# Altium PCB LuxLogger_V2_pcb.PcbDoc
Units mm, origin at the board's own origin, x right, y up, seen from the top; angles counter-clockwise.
Board outline 63.83 x 29.23 mm, 4 copper layers (Layer 1, Layer 2 - GND, Layer 3 - PWR, Layer 4), stack 1.57 mm thick; 85 components, 62 nets, 282 pads, 83 vias.
Unrouted connection lines stored in the file: 1.
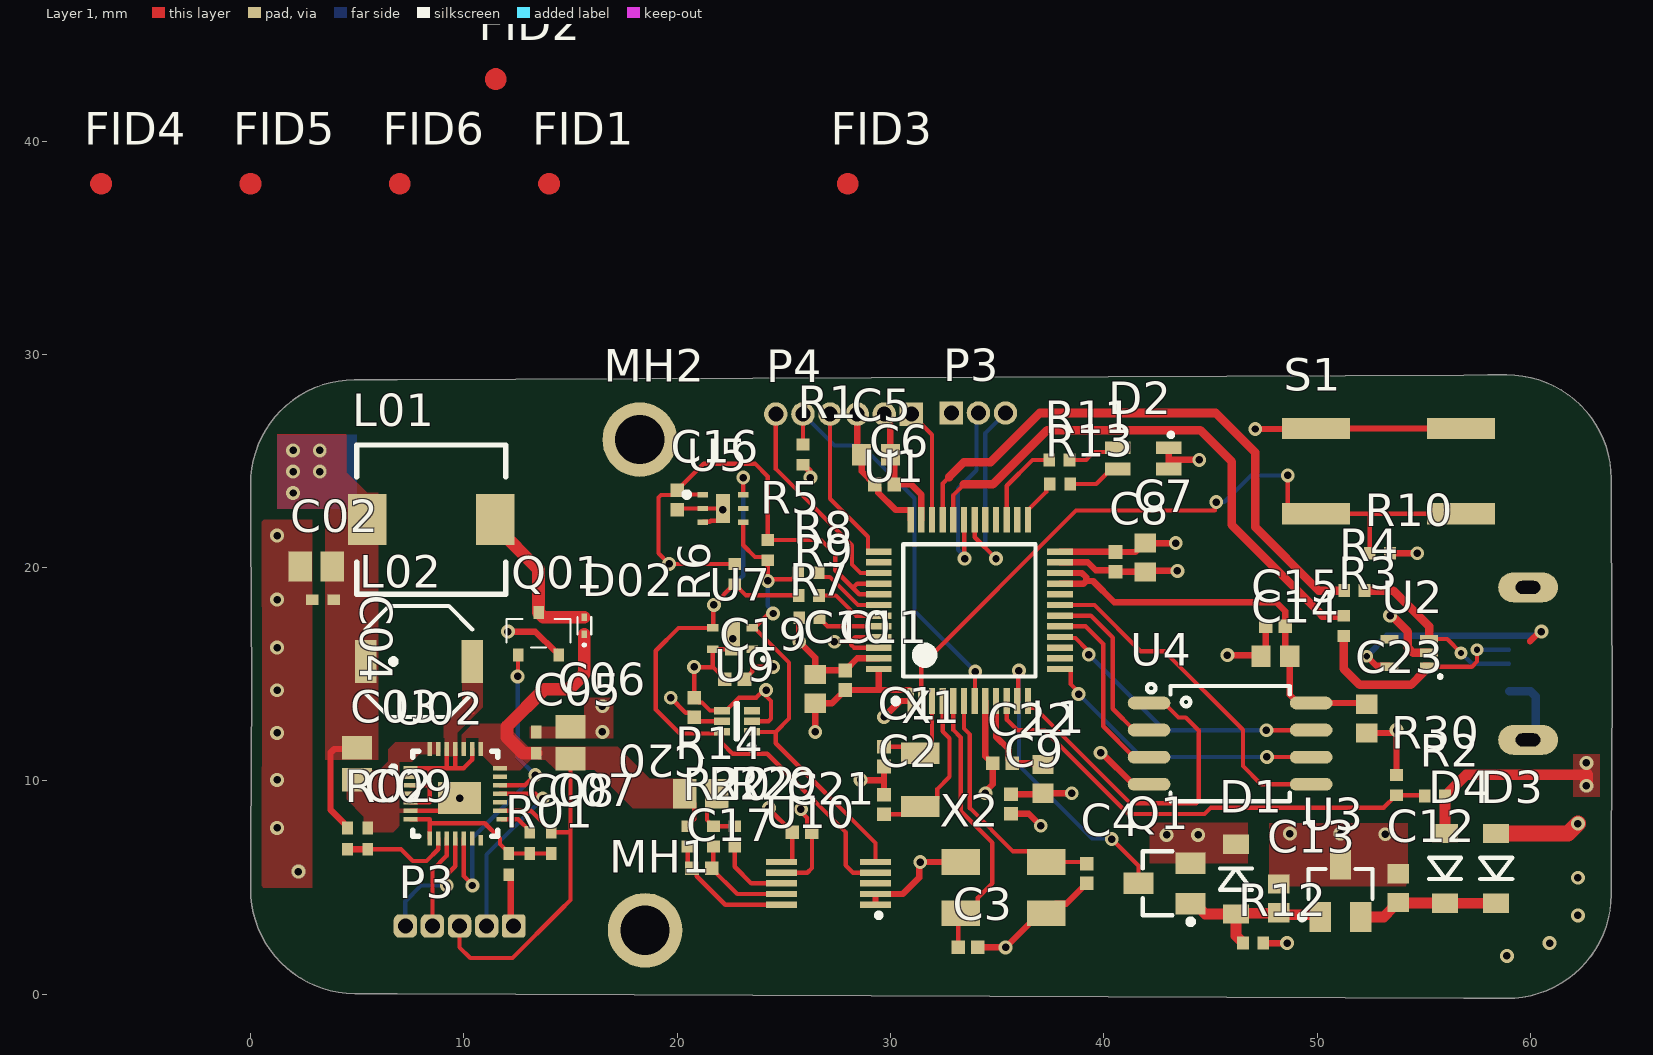
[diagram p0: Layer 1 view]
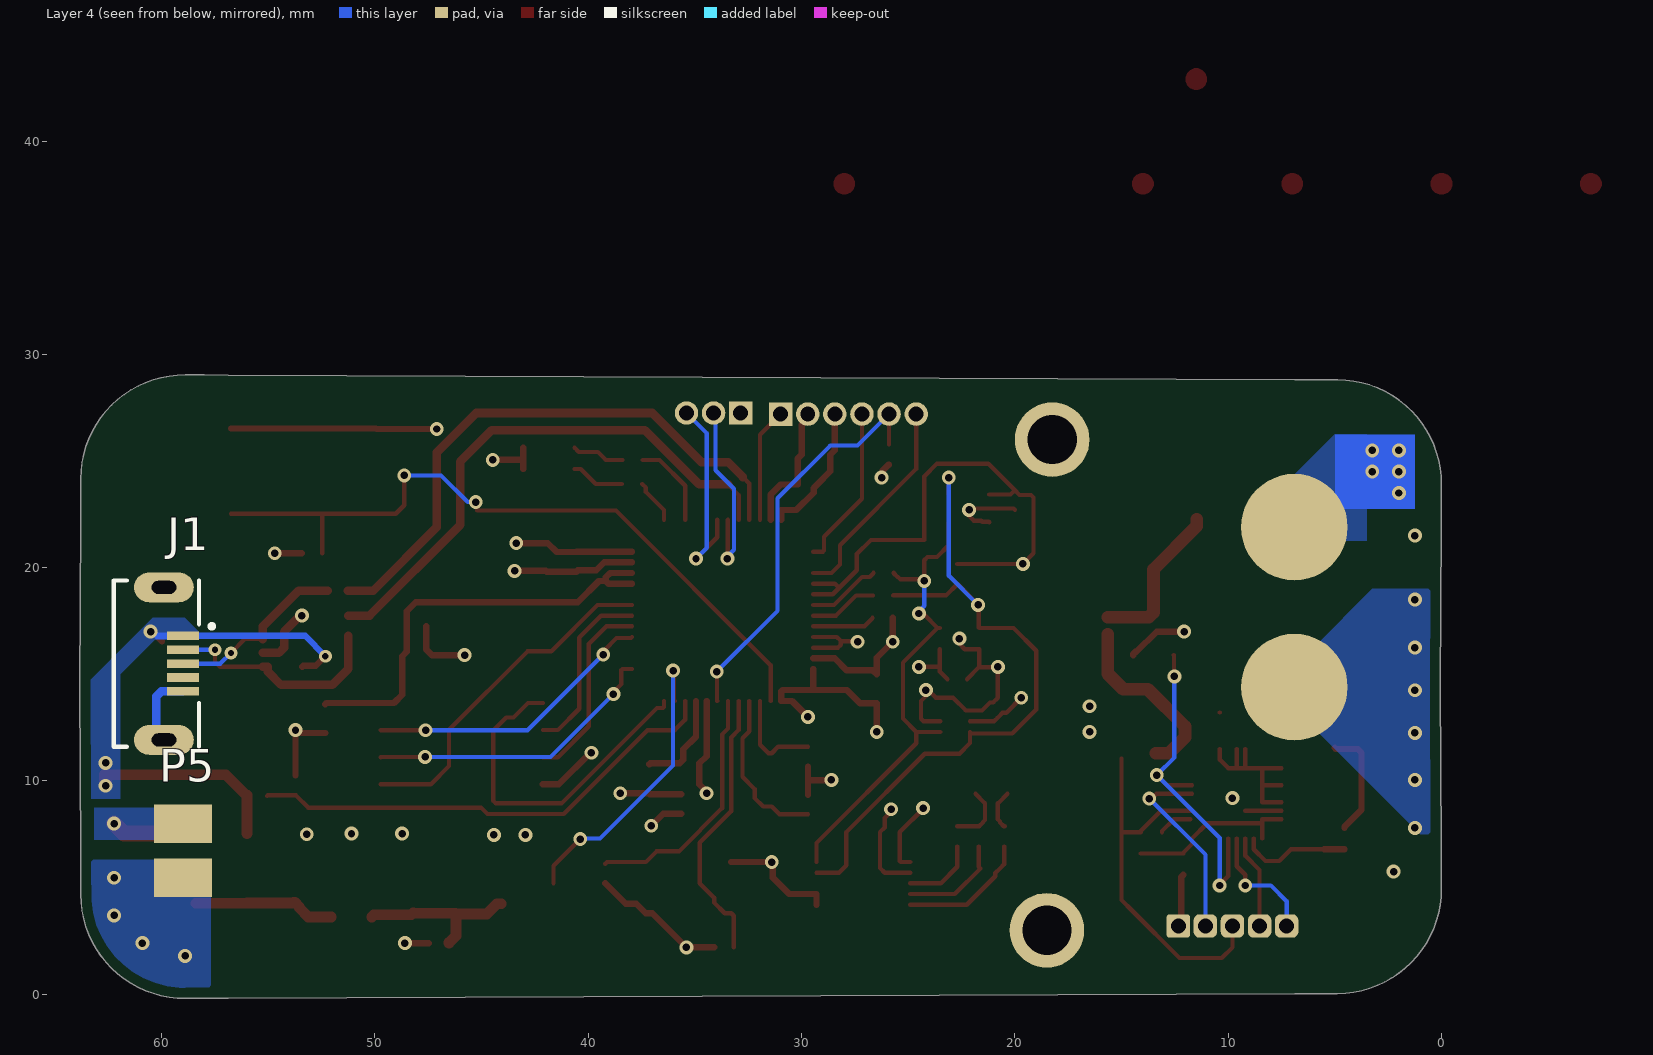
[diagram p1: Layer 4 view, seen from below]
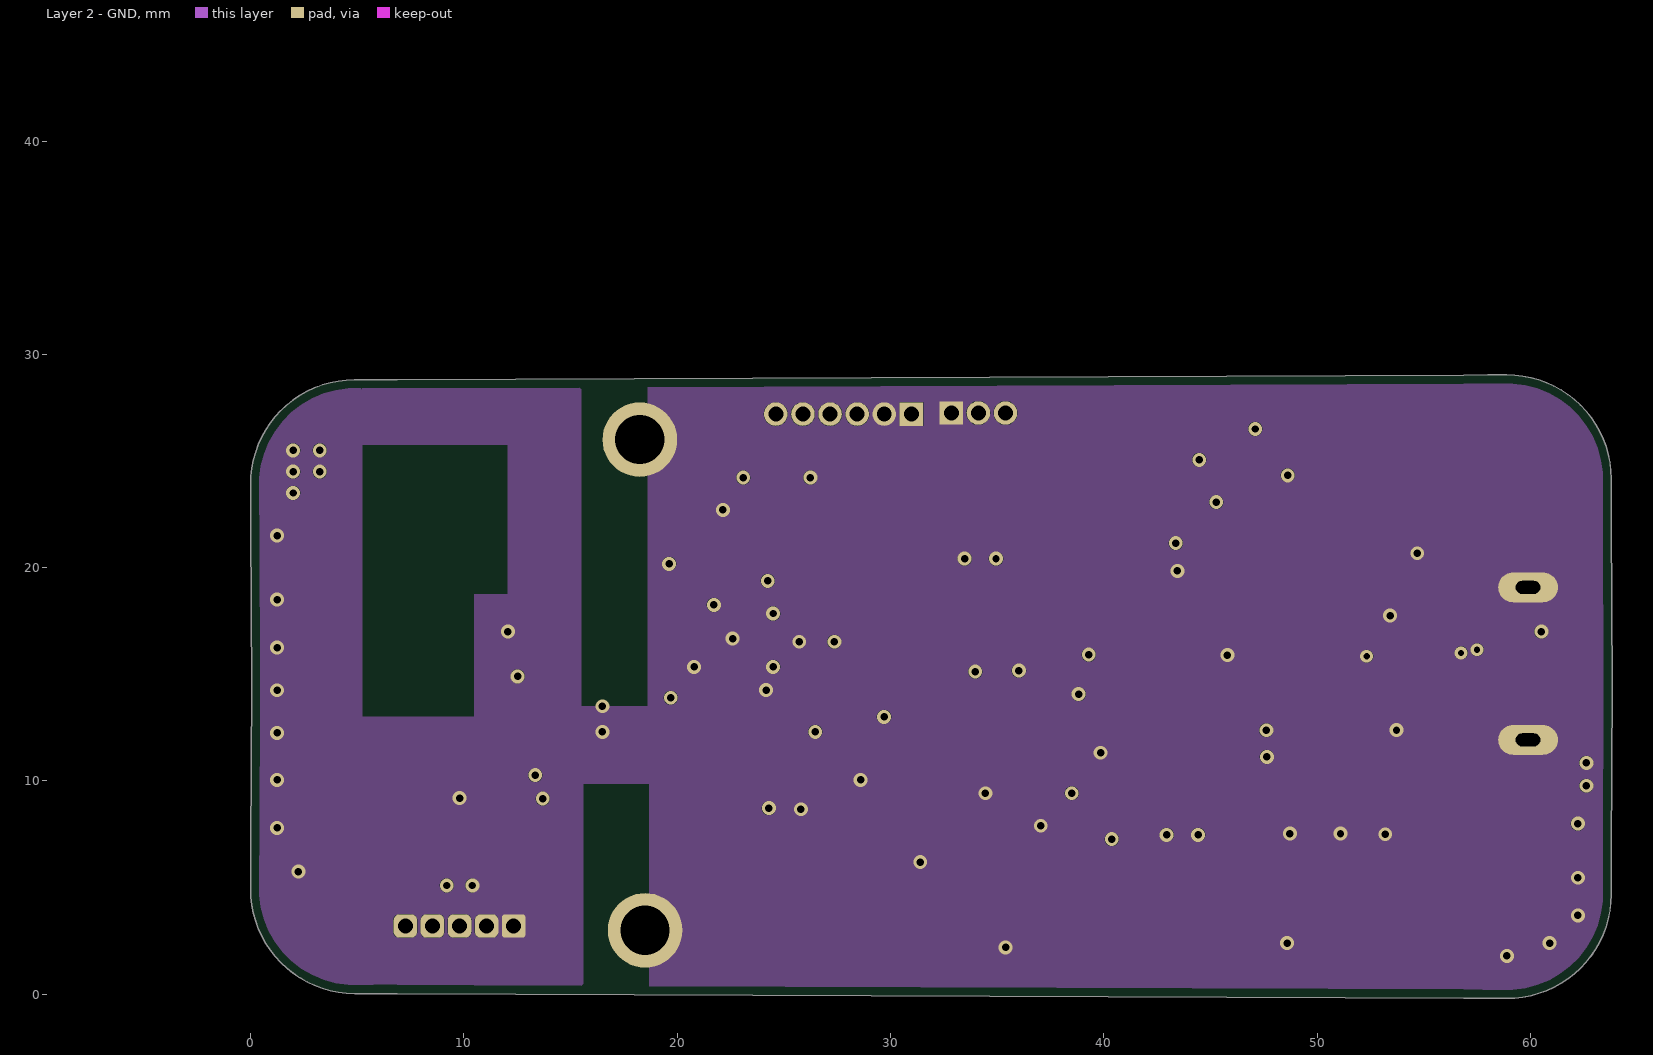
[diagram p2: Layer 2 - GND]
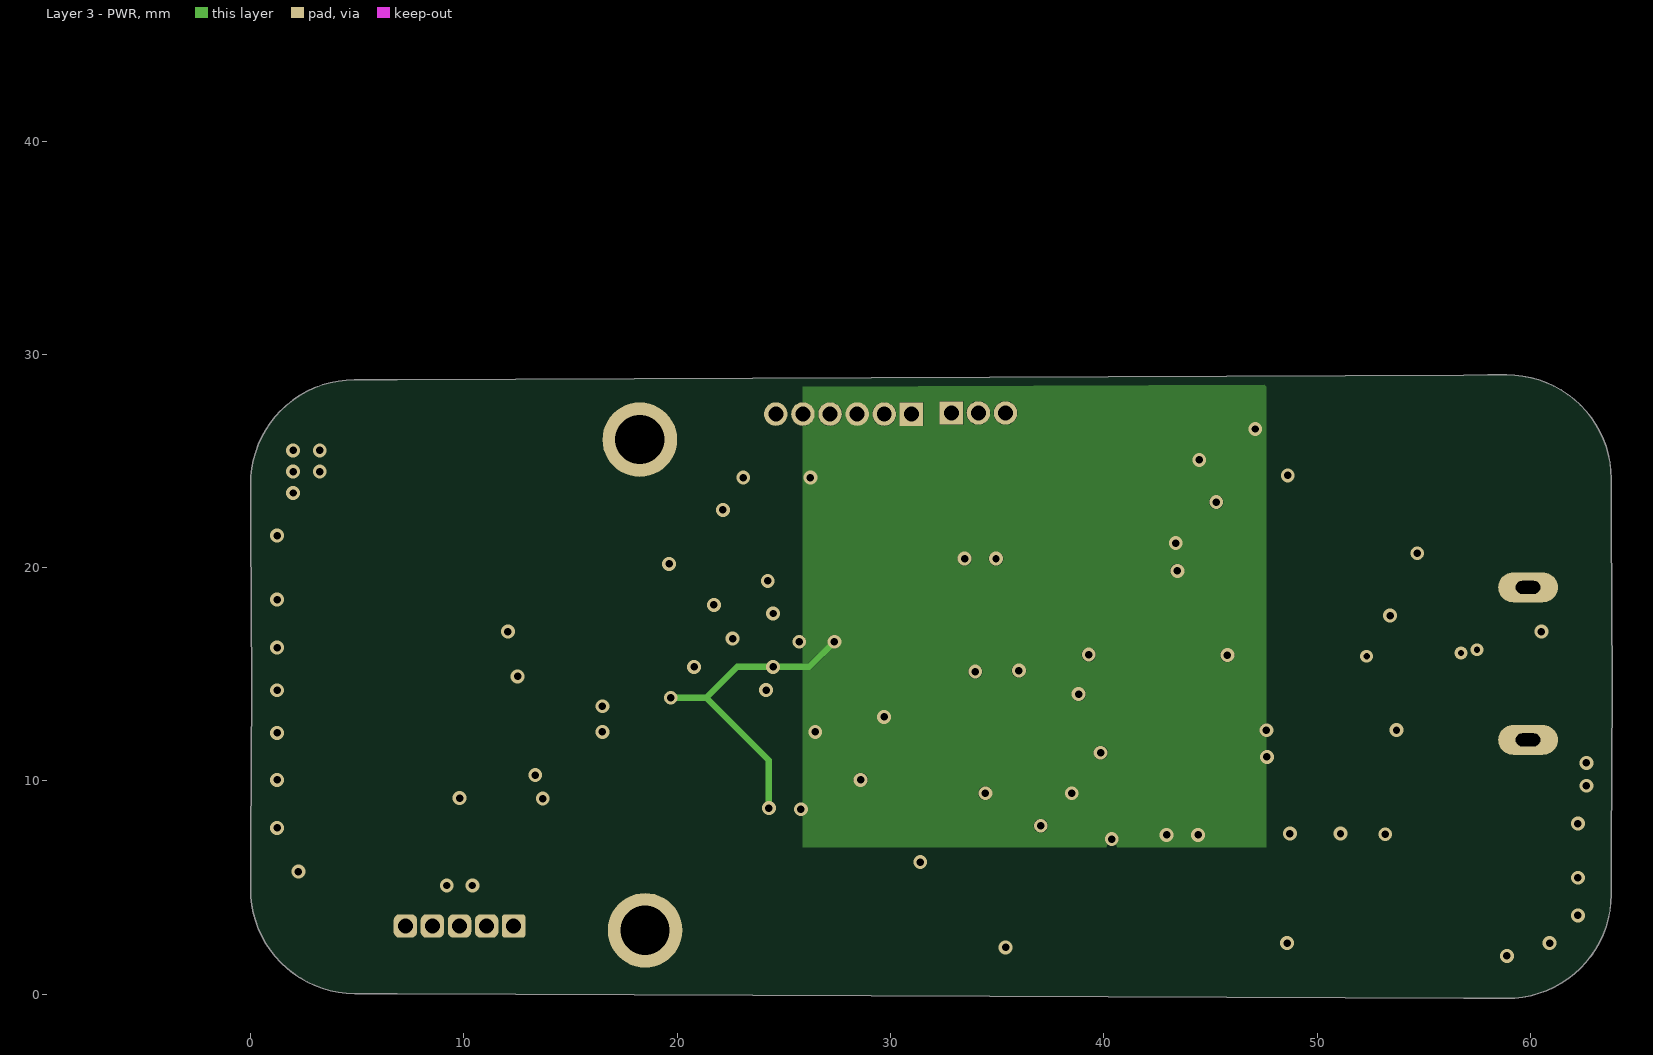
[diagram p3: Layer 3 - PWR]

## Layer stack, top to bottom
Top Solder: solder mask 0.01, Solder Resist, Dk 3.5
Layer 1: signal copper 0.035
Dielectric 1: core 0.36, FR-4, Dk 4.8
Layer 2 - GND: signal copper 0.035
Dielectric 3: prepreg 0.71, Dk 4.2
Layer 3 - PWR: signal copper 0.035
Dielectric 4: core 0.36, Dk 4.2
Layer 4: signal copper 0.035
Bottom Solder: solder mask 0.01, Solder Resist, Dk 3.5

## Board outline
4.878,0.035 cw(c4.896,4.925) 0.006,4.949 0.013,6.068 0.017,6.951 0.049,14.422 0.017,21.893 0.012,23.016 0.006,23.895 cw(c4.896,23.919) 4.878,28.809 5.998,28.811 6.881,28.815 56.881,29.027 58.004,29.032 58.883,29.037 cw(c58.907,24.148) 63.797,24.165 63.799,23.046 63.803,22.163 63.836,14.422 63.803,6.681 63.799,5.557 63.797,4.678 cw(c58.907,4.696) 58.883,-0.194 57.764,-0.187 56.881,-0.183 6.881,0.029 5.757,0.033

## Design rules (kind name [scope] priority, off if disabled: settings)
BoardOutlineClearance "BoardOutlineClearance inner layers" [OnLayer('Layer 2 - GND') OR OnLayer('Layer 3 - PWR')] p1: gap=0.4 ignorepadtopadclearanceinfootprint=FALSE
BoardOutlineClearance [OnLayer('Layer 1') OR OnLayer('Layer 4')] p2: gap=0.5 ignorepadtopadclearanceinfootprint=FALSE
Clearance "Clearance tmp112" [HasFootprint('SOTFL50P160X60-6N')] p1: gap=0.15 ignorepadtopadclearanceinfootprint=FALSE
Clearance "Clearance outer layers" [OnLayer('Layer 1') OR OnLayer('Layer 4')] p2: gap=0.2 ignorepadtopadclearanceinfootprint=FALSE
Clearance "Clearance inner layers" [OnLayer('Layer 2') OR OnLayer('Layer 3')] p3: gap=0.2 ignorepadtopadclearanceinfootprint=FALSE
ComponentClearance "ComponentClearance power options" [HasFootprint('BU2032SM-HD-G') vs HasFootprint('JST_S2B-PH-SM4-TB') OR HasFootprint('SOD123 SODFL360X130-2N')] p1: gap=0 collisioncheckmode=3 verticalgap=0 showdistances=FALSE
ComponentClearance "ComponentClearance power options_1" [All vs HasFootprint('HOLE_PLATED_2900um')] p2: gap=0 collisioncheckmode=3 verticalgap=0 showdistances=FALSE
ComponentClearance "ComponentClearance FID" [HasFootprint('FIDUCIAL_01')] p3: gap=0 collisioncheckmode=3 verticalgap=0 showdistances=FALSE
ComponentClearance [All] p4: gap=0.2 collisioncheckmode=3 verticalgap=2540 showdistances=FALSE
DiffPairsRouting "DiffPairsRouting USB 90R diff" [InDifferentialPair('USB')] p1: maxlimit=0.3 minlimit=0.15 mostfreqgap=0.3 toplayer_minwidth=0.2 toplayer_maxwidth=0.6 toplayer_prefwidth=0.6 midlayer1_mingap=0.254 midlayer1_maxgap=0.254 midlayer1_prefgap=0.254 midlayer1_minwidth=0.381 midlayer1_maxwidth=0.381 midlayer1_prefwidth=0.381 midlayer2_mingap=0.254 midlayer2_maxgap=0.254 midlayer2_prefgap=0.254 midlayer2_minwidth=0.381 midlayer2_maxwidth=0.381 midlayer2_prefwidth=0.381 bottomlayer_minwidth=0.2 bottomlayer_maxwidth=0.6 bottomlayer_prefwidth=0.6 maxuncoupledlength=12.7
HoleSize [All] p1: absolutevalues=TRUE maxlimit=4 minlimit=0.3 maxpercent=80.000 minpercent=20.000
PlaneClearance [All] p1: clearance=0.2
PlaneConnect [All] p1: planeconnectstyle=Direct reliefexpansion=0.508 reliefentries=4 reliefconductorwidth=0.254 reliefairgap=0.254
PolygonConnect [All] p1: connectstyle=Direct reliefconductorwidth=0.3 reliefentries=4 polygonreliefangle="90 Angle" airgapwidth=0.2
RoutingVias [All] p1: holewidth=0.3 width=0.6 viastyle="Through Hole" minholewidth=0.3 minwidth=0.6 maxholewidth=0.5 maxwidth=1
SolderMaskExpansion [All] p1: expansion=0.102 istentingtop=FALSE
UnRoutedNet [All] p1: checkbadconnections=TRUE
Width [All] p1: maxlimit=2 minlimit=0.15 preferedwidth=0.2 toplayer_minwidth=0.2 bottomlayer_minwidth=0.2 minimp=50.000000 maximp=50.000000 favimp=50.000000
24 further rules are at their usual default settings.

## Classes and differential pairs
component class Sunboost: C02 C03 C04 C05 C06 C07 C08 C09 D02 L01 L02 P3 Q01 R01 R02 U02
differential pair USB: +USB_P -USB_N

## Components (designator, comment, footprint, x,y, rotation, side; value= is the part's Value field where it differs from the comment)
C1 "" CAP0402 29.7,11.14 r90 top
C02 "Cap_0805" 0805 3.075,20.05 r0 top value=22uF
C2 "" CAP0402 29.7,8.9 r270 top
C03 "Cap_0805" 0805 5,10.8 r90 top value=22uF
C3 "" CAP0402 33.64,2.2 r180 top
C04 "Cap_0402" 0402 3.4,18.5 r0 top value=100nF
C4 "" CAP0402 39.2,5.66 r90 top
C05 "Cap_0402" 0402 13.4,11.8 r270 top value=100nF
C5 "" CAP0603 29.325,25.3 r180 top
C06 "Cap_0805" 0805 15,11.8 r270 top value=22uF
C6 "" CAP0402 29.725,23.9 r180 top
C07 "Cap_0402" 0402 14.1,7.1 r90 top value=100nF
C7 "" CAP0603 41.95,20.475 r90 top
C08 "Cap_0402" 0402 13.1,7.1 r90 top value=470nF
C8 "" CAP0402 40.55,20.275 r90 top
C09 "Cap_0402" 0402 5.5,7.3 r270 top value=100nF
C9 "" CAP0402 35.65,8.925 r90 top
C10 "" CAP0603 26.475,14.322 r270 top
C11 "" CAP0402 27.875,14.722 r270 top
C12 "" CAP0603 53.8,4.975 r270 top
C13 "" CAP0603 48.2,4.5 r270 top
C14 "" CAP0603 48.05,15.85 r0 top
C15 "" CAP0402 48.05,17.25 r0 top
C16 "" CAP0402 20,23.169 r90 top
C17 "" CAP0402 21.16,5.9 r180 top
C19 "" CAP0402 22.7,14.772 r0 top
C20 "" CAP0402 20.8,13.44 r270 top
C21 "" CAP0402 25.86,7.6 r180 top
C22 "" CAP0402 35.25,10.825 r0 top
C23 "" CAP0603 52.325,12.925 r90 top
D1 "Alternative ON BAT54T1GOSCT-ND" "SOD123 SODFL360X130-2N" 46.2,5.4 r90 top
D02 "NSR0140P2" SOD-923 15.65,16.875 r90 top
D2 "" KPTBD-3216SURKCGKC 40.65,25.625 r0 top
D3 "Alternative ON BAT54T1GOSCT-ND" "SOD123 SODFL360X130-2N" 58.4,5.9 r270 top
D4 "Alternative ON BAT54T1GOSCT-ND" "SOD123 SODFL360X130-2N" 56,5.9 r270 top
FID1 "Fiducial" FIDUCIAL_02_small 14,38 r90 top
FID2 "Fiducial" FIDUCIAL_02_small 11.5,42.9 r90 top
FID3 "Fiducial" FIDUCIAL_02_small 28,38 r90 top
FID4 "Fiducial" FIDUCIAL_02_small -7,38 r90 top
FID5 "Fiducial" FIDUCIAL_02_small 0,38 r90 top
FID6 "Fiducial" FIDUCIAL_02_small 7,38 r90 top
J1 "USB3140-30-0170-1-C_REVE1" GCT_USB3140-30-0170-1-C_REVE1 60.25,15.5 r270 bottom
L01 "SRR7045-102M" SRR7045-102M 5.475,22.25 r0 top value=X
L1 "" CAP0603 37.15,10.1 r90 top
L02 "SD53-4R7-R" SD53-4R7-R 7.9,15.6 r0 top value=X
MH1 "Mounting hole" HOLE_PLATED_2300um 18.5,3 r0 top
MH2 "Mounting hole" HOLE_PLATED_2300um 18.25,26 r0 top
P3 "1x5 Header" "1x5 Header 1.27" 12.34,3.2 r180 top
P3 "" "Header 1x3 1.27" 32.855,27.25 r0 top
P4 "" "Header 1x6 1.27" 30.98,27.2 r180 top
P5 "" "2x1 blank pads_2" 59,6.73 r270 bottom
Q01 "PMV130ENE" SOT-23 12.557,15.9 r0 top
Q1 "" SOT23-3 42.7,5.2 r180 top
R01 "Res_0402" 0402 12.1,6.1 r270 top value=0
R1 "" RES0402 25.9,25.3 r270 top
R02 "Res_0402" 0402 4.55,7.3 r270 top value=51K
R2 "" RES0402 55.525,9.3 r0 top
R3 "" RES0402 51.25,17.275 r270 top
R4 "" RES0402 51.75,18.925 r0 top
R5 "" RES0402 24.25,20.825 r90 top
R6 "" RES0402 22.7,19.7 r90 top
R7 "" RES0402 26.2,17.65 r0 top
R8 "" RES0402 26.151,19.765 r0 top
R9 "" RES0402 26.176,18.69 r0 top
R10 "" RES0402 52.95,20.675 r180 top
R11 "" RES0402 37.925,25.05 r180 top
R12 "" RES0402 47,2.4 r180 top
R13 "" RES0402 37.95,23.925 r180 top
R14 "Res_0805" 0805 21.1,9.4 r180 top value=1K
R20 "" RES0402 20.5,7.4 r270 top
R22 "" RES0402 21.7,7.4 r270 top
R29 "" RES0402 22.7,7.4 r270 top
R30 "" RES0402 53.725,9.8 r270 top
S1 "" EVQQ2W02W 56.75,26.525 r180 top
U1 "" TSQFP50P900X900X160-48N 33.7,18 r90 top
U02 "Sunboost 3" 28-QFN_0.4mm 7.5,10.6 r0 top
U2 "" "SC-70 5L" 55.25,15.35 r90 top
U3 "" SOT23-3 51.1,5 r90 top
U4 "" SO_8_W 45.925,11.75 r0 top
U5 "" OPT3001 21.2,23.425 r0 top
U7 "" SHTC3 23.525,16.172 r90 top
U9 "" SOTFL50P160X60-6N 22.8,12.8 r180 top
U10 "" VSSOP-10 27.2,5.2 r180 top
X1 "" FC-135 31.4,11.3 r270 top
X2 "" ABM3B 35.3,5 r0 top

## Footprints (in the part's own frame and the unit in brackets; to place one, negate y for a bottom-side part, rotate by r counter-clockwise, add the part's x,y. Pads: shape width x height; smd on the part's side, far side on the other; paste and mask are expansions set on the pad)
"1x5 Header 1.27" [mm]
  rrect25% 1.1x1.1 hole 0.7 paste+0 mask+0: 1(0,0)
  rrect50% 1.1x1.1 hole 0.7 paste+0 mask+0: 2(1.27,0) 3(2.54,0) 4(3.81,0) 5(5.08,0)
"2x1 blank pads_2" [mm]
  rect 1.8x2.7 smd: 1(-1.27,0) 2(1.27,0)
28-QFN_0.4mm [mm]
  rect 0.65x0.2 smd mask+0.05: 1(0,0) 2(0,-0.4) 3(0,-0.8) 4(0,-1.2) 5(0,-1.6) 6(0,-2) 7(0,-2.4) 16(4.2,-2) 17(4.2,-1.6) 18(4.2,-1.2) 19(4.2,-0.8) 20(4.2,-0.4) 21(4.2,0)
  rect 0.2x0.65 smd mask+0.05: 8(0.9,-3.3) 9(1.3,-3.3) 10(1.7,-3.3) 11(2.1,-3.3) 12(2.5,-3.3) 13(2.9,-3.3) 22(3.3,0.9) 23(2.9,0.9) 24(2.5,0.9) 25(2.1,0.9) 26(1.7,0.9) 27(1.3,0.9) 28(0.9,0.9)
  rect 0.2x0.5 smd mask+0.05: 14(3.3,-3.375)
  rect 0.5x0.2 smd mask+0.05: 15(4.275,-2.4)
  rect 2x1.5 smd mask+0.05: 29(2.3,-1.4)
  silkscreen extent -0.9,-3.2 4.1,0.8, body extent 0.1,-3.2 4.1,0.8, height 0.75
0402 [mm] "Chip Capacitor, Body 1.0x0.5mm, IPC High Density"
  rect 0.6x0.5 smd: 1(-0.5,0) 2(0.5,0)
  body extent -0.55,-0.3 0.55,0.3, height 1.3
0805 [mm] "Chip Capacitor, Body 2.0x1.3mm, IPC High Density"
  rect 1.1x1.4 smd: 1(-0.75,0) 2(0.75,0)
  body extent -1.1,-0.72 1.1,0.72, height 1.4
ABM3B [mm]
  rect 1.8x1.2 smd: 1(-2,-1.2) 2(2,-1.2) 3(2,1.2) 4(-2,1.2)
  body extent -2.5,-1.6 2.5,1.6, height 1.1
CAP0402 [mm]
  rect 0.64x0.64 smd: 1(-0.46,0) 2(0.46,0)
  body extent -0.55,-0.3 0.55,0.3, height 0.6
CAP0603 [mm]
  rect 0.9x1 smd: 1(-0.675,0) 2(0.675,0)
  body extent -0.87,-0.48 0.87,0.47, height 0.85
EVQQ2W02W [mm]
  rect 3.2x1 smd: 1(0,0) 2(6.8,0) 3(6.8,4) 4(0,4)
  body extent 0,-1 6.5,5, height 2.5
FC-135 [mm]
  rect 1x1.8 smd: 1(0,0) 2(2.5,0)
  body extent -0.35,-0.75 2.85,0.75, height 0.8
FIDUCIAL_02_small [mm]
  Layer 1 region: 0,-0.5 -0.099,-0.5 -0.283,-0.424 -0.424,-0.283 -0.5,-0.099 -0.5,0 -0.5,0.099 -0.424,0.283 -0.283,0.424 -0.099,0.5 0,0.5 0.099,0.5 0.283,0.424 0.424,0.283 0.5,0.099 0.5,0 0.5,-0.099 0.424,-0.283 0.283,-0.424 0.099,-0.5 0,-0.5
  Layer 1 pour cut-out: 0,-1 -0.098,-1 -0.292,-0.962 -0.474,-0.886 -0.637,-0.777 -0.777,-0.637 -0.886,-0.474 -0.962,-0.292 -1,-0.098 -1,0 -1,0.098 -0.962,0.292 -0.886,0.474 -0.777,0.637 -0.637,0.777 -0.474,0.886 -0.292,0.962 -0.098,1 0,1 0.098,1 0.292,0.962 0.474,0.886 0.637,0.777 0.777,0.637 0.886,0.474 0.962,0.292 1,0.098 1,0 1,-0.098 0.962,-0.292 0.886,-0.474 0.777,-0.637 0.637,-0.777 0.474,-0.886 0.292,-0.962 0.098,-1 0,-1
GCT_USB3140-30-0170-1-C_REVE1 [mm]
  rect 0.4x1.5 smd: 1(-1.3,1.25) 2(-0.65,1.25) 3(0,1.25) 4(0.65,1.25) 5(1.3,1.25)
  oval 1.4x2.8 hole 0.6 slot 1.15 at 90 deg mask+0: S1(-3.575,0.36) S2(3.575,0.36)
  silkscreen extent -3.9,-2 3.9,2.7
"Header 1x3 1.27" [mm]
  rect 1.1x1.1 hole 0.7: 1(0,0)
  round 1.1 hole 0.7: 2(1.27,0) 3(2.54,0)
"Header 1x6 1.27" [mm]
  rect 1.1x1.1 hole 0.7: 1(0,0)
  round 1.1 hole 0.7: 2(1.27,0) 3(2.54,0) 4(3.81,0) 5(5.08,0) 6(6.35,0)
HOLE_PLATED_2300um [mm]
  round 3.5 hole 2.3: 1(0,0)
KPTBD-3216SURKCGKC [mm]
  rect 1.2x0.6 smd: 1(2.4,0) 2(0,0) 3(2.4,-1) 4(0,-1)
  silkscreen extent 2.4,0.5 2.6,0.7, body extent -0.4,-1.3 2.8,0.3, height 1.8
OPT3001 [mm]
  rect 0.5x0.25 smd: 1(0,0) 2(0,-0.65) 3(0,-1.3) 4(1.9,-1.3) 5(1.9,-0.65) 6(1.9,0)
  rect 0.65x1.35 smd: 7(0.95,-0.65)
  silkscreen extent -0.87,-0.12 -0.63,0.12, body extent -0.05,-1.65 1.95,0.35, height 0.62
RES0402 [mm]
  rect 0.55x0.6 smd: 1(-0.475,0) 2(0.475,0)
  body extent -0.55,-0.3 0.55,0.3, height 0.4
"SC-70 5L" [mm]
  rect 0.4x0.85 smd: 1(0,0) 2(0.65,0) 3(1.3,0) 4(1.3,1.85) 5(0,1.85)
  silkscreen extent -0.51,-0.58 -0.4,-0.47, body extent -0.45,0.25 1.75,1.6, height 1.1
SD53-4R7-R [mm]
  rect 1x2 smd mask+0.05: 1(-2.5,0) 2(2.5,0)
  silkscreen extent -2.5,-2.6 2.5,2.6, body extent -2.6,-2.6 2.6,2.6, height 3
SHTC3 [mm]
  rect 0.35x0.55 smd: 1(0,0) 2(1,0) 3(1,1.85) 4(0,1.85)
  rect 1.6x0.7 smd: 5(0.5,0.925)
  silkscreen extent -0.51,-0.58 -0.4,-0.47, body extent -0.5,-0.07 1.5,1.93, height 0.75
SO_8_W [mm]
  oval 2x0.6 smd: 1(-3.8,1.905) 2(-3.8,0.635) 3(-3.8,-0.635) 4(-3.8,-1.905) 5(3.8,-1.905) 6(3.8,-0.635) 7(3.8,0.635) 8(3.8,1.905)
  silkscreen extent -3.9,-2.7 2.8,2.8, body extent -4.05,-2.73 4.05,2.73, height 1.75
"SOD123 SODFL360X130-2N" [mm]
  rect 0.91x1.22 smd: 1(-1.635,0) 2(1.635,0)
  silkscreen extent -0.5,-0.75 0.5,0.75, body extent -1.4,-0.85 1.4,0.85, height 1.3
SOD-923 [mm]
  rect 0.36x0.25 smd mask+0.05: 1(0,0) 2(0.8,0)
  silkscreen extent -0.52,-0.33 0.8,0.33, body extent -0.12,-0.32 0.93,0.32, height 0.43
SOT23-3 [mm]
  rect 1.4x1 smd: 1(-1.375,0.95) 2(-1.375,-0.95) 3(1.075,0)
  silkscreen extent -1.5,-1.5 0.87,1.92, body extent -1.7,-1.5 1.3,1.5, height 1.1
SOT-23 [mm]
  rect 0.5x0.6 smd mask+0.05: 1(0,0) 2(1.9,0) 3(0.95,2)
  silkscreen extent -0.55,0.35 2.45,1.7, body extent -0.55,-0.25 2.45,2.25, height 1.1
SOTFL50P160X60-6N [mm]
  rect 0.75x0.35 smd: 1(-0.7,0.5) 2(-0.7,0) 3(-0.7,-0.5) 4(0.7,-0.5) 5(0.7,0) 6(0.7,0.5)
  silkscreen extent -0.83,-0.85 0.05,1.35, body extent -0.85,-0.85 0.85,0.85, height 0.6
SRR7045-102M [mm]
  rect 1.8x2.4 smd mask+0.05: 1(0,0) 2(6,0)
  silkscreen extent -0.5,-3.5 6.5,3.5, body extent -0.5,-3.5 6.5,3.5, height 4.5
TSQFP50P900X900X160-48N [mm]
  rect 1.2x0.3 smd: 1(-4.25,2.75) 2(-4.25,2.25) 3(-4.25,1.75) 4(-4.25,1.25) 5(-4.25,0.75) 6(-4.25,0.25) 7(-4.25,-0.25) 8(-4.25,-0.75) 9(-4.25,-1.25) 10(-4.25,-1.75) 11(-4.25,-2.25) 12(-4.25,-2.75) 25(4.25,-2.75) 26(4.25,-2.25) 27(4.25,-1.75) 28(4.25,-1.25) 29(4.25,-0.75) 30(4.25,-0.25) 31(4.25,0.25) 32(4.25,0.75) 33(4.25,1.25) 34(4.25,1.75) 35(4.25,2.25) 36(4.25,2.75)
  rect 0.3x1.2 smd: 13(-2.75,-4.25) 14(-2.25,-4.25) 15(-1.75,-4.25) 16(-1.25,-4.25) 17(-0.75,-4.25) 18(-0.25,-4.25) 19(0.25,-4.25) 20(0.75,-4.25) 21(1.25,-4.25) 22(1.75,-4.25) 23(2.25,-4.25) 24(2.75,-4.25) 37(2.75,4.25) 38(2.25,4.25) 39(1.75,4.25) 40(1.25,4.25) 41(0.75,4.25) 42(0.25,4.25) 43(-0.25,4.25) 44(-0.75,4.25) 45(-1.25,4.25) 46(-1.75,4.25) 47(-2.25,4.25) 48(-2.75,4.25)
  silkscreen extent -4.37,-3.1 3.1,3.57, body extent -3.5,-3.5 3.5,3.5, height 1.6
VSSOP-10 [mm]
  rect 1.45x0.3 smd: 1(-2.1,1) 2(-2.1,0.5) 3(-2.1,0) 4(-2.1,-0.5) 5(-2.1,-1) 6(2.3,-1) 7(2.3,-0.5) 8(2.3,0) 9(2.3,0.5) 10(2.3,1)
  silkscreen extent -2.35,1.4 -2.15,1.6, body extent -2.35,-1.5 2.55,1.5, height 1.15

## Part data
C1 C2 C3 C4 C6 C8 C9 C11 C15 C16 C17 C19 C20 C21 C22: library part Cap, "Capacitor", Package=0402
C02 C03 C04 C05 C06 C07 C08 C09: "Capacitor"
C5 C7 C10 C12 C13 C14 C23: library part Cap, "Capacitor", Package=0603
D1 D3 D4: library part "D Schottky", "Schottky Diode", Manufacturer=NEXPERIA, Manufacturer PN=BAT54GW, Package=SOD123
D02: "Typical INFRARED GaAs LED"
D2: library part LED_RG, "Red/green LED", Manufacturer=KINGBRIGHT, Manufacturer PN=KPTBD-3216SURKCGKC, Package=SMD
J1: "USB - micro B USB 2.0 Receptacle Connector 5 Position Surface Mount, Through Hole", Package=None
L01 L02: "Inductor"
L1: library part Inductor, "Inductor", Manufacturer=MURATA, Manufacturer PN=BLM18AG601SN1D, Package=0603
P3: library part "Header 3", "Header, 3-Pin", Package=Hole
P4: library part "Header 6", "Header, 6-Pin", Package=Hole
P5: library part "Header 2", "Header, 2-Pin", Package=SMD
Q01: "N-Channel MOSFET"
Q1: library part MOSFET-P, "P-Channel MOSFET", Manufacturer=ON, Manufacturer PN=FDN342P, Package=SOT-23
R01 R02 R14: "Resistor"
R1 R2 R3 R4 R5 R6 R7 R8 R9 R10 R11 R12 R13 R20 R22 R29 R30: library part Res2, "Resistor", Package=0402
S1: library part SW_EVQQ2, "Switch", Manufacturer=PANASONIC, Manufacturer PN=EVQQ2W02W, Package=SMD
U1: library part STM32L412CB_2, "MCU", Manufacturer=ST, Manufacturer PN=STM32L412CBT6, Package=LQFP-48
U02: "Initvation Sunboost 3"
U2: library part RClamp0503F, "TVS array USB", Manufacturer=SEMTECH, Manufacturer PN=RClamp0503F.TCT, Package=SC70-5L
U3: library part MCP1810TxxxTT, "3V3 LDO low iq", Manufacturer=MICROCHIP, Manufacturer PN=MCP1810T33ITT, Package=SOT23
U4: library part MX25R6435F_SO8, "ULTRA LOW POWER, 64M-BIT FLASH MEMORY", Manufacturer=Macronix, Manufacturer PN=MX25R6435FM2IL0, Package=SOIC-8
U5: library part OPT3001, "Lux sensor", Manufacturer=TI, Manufacturer PN=OPT3001DNP, Package=DNP-6
U7: library part SHTC3, "SHTC3 RH sensor", Manufacturer=SENSIRION, Package=DFN
U9: library part TMP112A, "Temp_Sensor", Manufacturer=TI, Manufacturer PN=TMP112AIDR, Package=SOT-563
U10: "Current and power monitor", Manufacturer=TI, Manufacturer PN=INA226AIDGS, Package=VSSOP10
X1: "32.768 kHz Crystal", Manufacturer=EPSON, Manufacturer PN="FC-135 32.7680KA-A5", Package=SMD
X2: "Crystal", Manufacturer=ABRACON, Manufacturer PN=ABM3B-8.000MHZ-B2-T, Package=SMD

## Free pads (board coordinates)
  round 5 smd far side mask+0.05: 1(6.9,14.4) 2(6.9,21.9)

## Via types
v1: diameter 0.65, hole 0.35, Layer 1 to Layer 4, tented both sides, 80 vias
v2: diameter 0.6, hole 0.3, Layer 1 to Layer 4, 3 vias

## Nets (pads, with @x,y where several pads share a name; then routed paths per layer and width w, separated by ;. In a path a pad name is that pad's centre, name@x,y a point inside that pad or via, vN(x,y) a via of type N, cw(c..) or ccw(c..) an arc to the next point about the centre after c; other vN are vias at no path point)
5V_USB: D4.1 J1.1 R2.2 U2.5 | length 20
  Layer 1 w0.3: v2(52.325,15.85) 52.782,15.393 53.357,15.393 U2.5 ; 59.984,16.55 60.434,17 v1(60.515,17)
  Layer 1 w0.5: D4.1 R2.2 56,9.325 56.025,9.35 56.05,9.35 56.989,10.289 62.625,10.289
  Layer 1 w0.6: v1(62.625,9.775) 62.625,10.289
  Layer 4 w0.3: v2(52.325,15.85) 53.275,16.8 J1.1 60.234,16.8 60.434,17 v1(60.515,17)
  other v1: 62.625,10.85
ACTIVATE_IV_MEASn: U1.20
BAT_MEAS: Q1.3 U1.11 | length 14.3
  Layer 1 w0.2: U1.11 35.987,13.787 35.987,15.137 v1(36.025,15.175) ; v1(40.375,7.275) 41.625,6.025 Q1.3
  Layer 4 w0.2: v1(36.025,15.175) 36.025,10.725 39.449,7.301 40.349,7.301 v1(40.375,7.275)
BUTTON: R10.2 S1.3 S1.4 U1.2 | length 34.3
  Layer 1 w0.2: U1.2 31.45,15.424 38.701,22.675 45.201,22.675 45.201,23.001 v1(45.275,23.075) ; v1(48.625,24.325) 48.625,22.925 49.025,22.525 S1.3 52.48,22.525 ; R10.2 52.475,22.52 52.48,22.525 ; S1.4 52.48,22.525
  Layer 4 w0.2: v1(45.275,23.075) 45.65,23.075 46.9,24.325 v1(48.625,24.325)
DGND: C07.1 C08.1 R01.1 U02.7 U02.8 | length 8.3
  Layer 1 w0.2: U02.7 8.4,8.2 8.4,8.015 ; U02.8 8.4,8.015 ; C07.1 C08.1 R01.1 12.1,6.65 11.7,7.05 11.7,7.3 10.985,8.015 8.4,8.015
EXT_BAT: D3.1 P5.1 R14.1 R22.1 R29.1 | length 6.9
  Layer 1 w0.2: R14.1 21.4,8.95 21.4,8.175 21.5,8.075 21.5,8.05 21.675,7.875 R22.1 R29.1
  Layer 1 w0.75: D3.1 61.76,7.535 v1(62.225,8)
FLASH_CS: U1.12 U4.1 | length 16.4
  Layer 1 w0.2: U1.12 36.45,13.467 36.5,13.417 36.783,13.417 41.25,8.95 44.333,8.95 44.45,9.067 44.45,12.375 43.848,12.977 43.503,12.977 42.825,13.655 U4.1
FLASH_SCLK: U1.13 U4.6 | length 13.9
  Layer 1 w0.2: U1.13 38.4,15.25 38.45,15.2 38.45,14.549 38.825,14.174 v1(38.825,14.075) ; v1(47.65,11.125) 47.655,11.12 49.72,11.12 U4.6
  Layer 4 w0.2: v1(38.825,14.075) 41.775,11.125 v1(47.65,11.125)
FLASH_SIO0: U1.19 U4.5 | length 16.3
  Layer 1 w0.2: U1.19 39.563,18.25 41.738,16.075 42.85,16.075 46.525,12.4 46.525,10.7 47.38,9.845 U4.5
FLASH_SIO1: U1.18 U4.2 | length 8.3
  Layer 1 w0.2: U1.18 39.393,17.75 40.425,16.718 40.425,13.385 41.425,12.385 U4.2
FLASH_SIO2: U1.17 U4.3 | length 9
  Layer 1 w0.2: U1.17 39.15,17.25 39.975,16.425 39.975,12.565 41.425,11.115 U4.3
FLASH_SIO3: U1.16 U4.7 | length 13.7
  Layer 1 w0.2: U1.16 38,16.7 38.674,16.7 39.223,16.151 39.223,16.002 v1(39.3,15.925) ; v1(47.625,12.375) 47.63,12.38 49.72,12.38 U4.7
  Layer 4 w0.2: v1(39.3,15.925) 42.85,12.375 v1(47.625,12.375)
GND: C1.1 C02.1 C2.1 C03.1 C3.1 C04.1 C4.1 C5.1 C05.1 C06.1 C6.1 C7.1 C8.1 C9.1 C09.1 C10.1 C11.1 C12.1 C13.1 C14.1 C15.1 C16.1 C19.1 C20.1 C21.1 C22.1 C23.1 J1.5 J1.S1 J1.S2 MH1.1 MH2.1 P3.1 P4.2 P5.2 pad.1 Q01.2 R01.2 R7.1 R10.1 R12.1 R30.1 U1.8 U1.23 U1.35 U1.47 U2.2 U02.2 U02.4 U02.6 U02.27 U02.28 U02.29 U3.3 U4.4 U5.2 U5.3 U5.7 U7.4 U7.5 U9.2 U9.4 U10.1 U10.2 U10.7 X2.2 X2.4 | length 83.8
  Layer 1 w0.2: U02.6 U02.29@9.2,8.6 ; C16.1 20.066,22.775 U5.2 U5.7 v1(22.15,22.709) 22.15,22.425 21.925,22.2 21.575,22.2 21.525,22.15 21.225,22.15 U5.3 ; C19.1 21.675,15.337 ; v1(22.6,16.672) 22.6,16.422 22.35,16.172 U7.4 21.675,15.337 ; U9.2 24.28,12.8 24.397,12.917 24.397,13.753 24.175,13.975 v1(24.175,14.262) 24.067,14.262 23.705,13.9 22.9,13.9 22.3,13.3 U9.4 21.537,13.3 21.42,13.417 21.42,13.424 21.164,13.68 21.02,13.68 C20.1 v1(20.8,15.35) 20.813,15.337 21.675,15.337 ; U10.7 26.1,5.7 26.32,5.92 C21.1 26.1,7.82 26.1,8.267 25.8,8.567 v1(25.8,8.675)
  Layer 1 w0.3: v1(12.07,17) 13.357,17 14.307,16.05 14.357,16.05 14.457,15.95 Q01.2 ; R01.2 12.2,5.5 12.2,3.34 P3.1@12.34,3.2 ; R7.1 v1(25.725,16.525) 26.475,15.775 C10.1 26.66,15.182 C11.1 28.443,15.75 U1.47 ; v1(28.6,10.05) 28.622,10.028 29.7,10.028 ; U10.1 U10.2 30.575,4.7 31.343,5.468 31.343,6.143 v1(31.4,6.2) X2.4 ; C2.1 29.7,10.028 ; C1.1 29.7,10.028 ; P4.2 29.71,26.984 30,26.694 C5.1 30.185,25.115 C6.1 30.98,23.9 31.45,23.43 U1.35 ; C3.1 v1(35.4,2.2) 37,3.8 X2.2 37.75,4.25 38.25,4.25 C4.1 ; v1(34.45,9.425) 34.45,9.506 34.79,9.846 C22.1 34.45,11.165 U1.8 ; C9.1 36.485,8.465 v1(37.05,7.9) ; U1.23 39.258,20.25 39.633,19.875 40.49,19.875 C8.1 41.935,19.815 C7.1 42,19.85 v1(43.45,19.85) ; v1(39.85,11.325) 39.897,11.325 41.377,9.845 U4.4 ; v1(45.8,15.9) 47.325,15.9 47.59,16.165 C15.1 ; R12.1 v1(48.6,2.4) ; C23.1 53.509,12.25 53.644,12.385 v1(53.725,12.385) R30.1 ; R10.1 v1(54.7,20.675)
  Layer 1 w0.4: v1(53.425,17.75) 53.493,17.75 53.618,17.625 53.626,17.625 54.25,17.001 54.25,16.25 54.5,16 U2.2
  Layer 4 w0.4: J1.5 60.016,14.2 60.25,13.966 60.25,12.285 J1.S2
  other v1: 58.9,1.8 60.9,2.4 62.225,3.7 62.225,5.46 2.25,5.75 53.2,7.5 48.725,7.535 51.1,7.535 1.25,7.8 9.8,9.2 1.25,10.05 1.25,12.25 16.5,12.3 16.5,13.5 1.25,14.25 1.25,16.25 1.25,18.5 1.25,21.5
I2C1_SCL: R5.1 R8.1 U5.4 U7.2 U9.1 U10.5 | length 22.9
  Layer 1 w0.2: U5.4 23.1,21.05 23.65,20.5 24.1,20.5 R5.1 v1(24.25,19.375) 24.325,19.45 25.361,19.45 25.476,19.565 25.501,19.565 25.676,19.74 R8.1 ; U9.1 24.625,12.3 ; U7.2 U7.2@23.625,17.172 ; v1(24.5,17.85) 24.423,17.773 24.227,17.773 U7.2@23.625,17.172 ; U10.5 29.3,7.09 24.625,11.765 24.625,12.3 ; U7.2@23.625,17.172 25.25,15.547 25.25,12.925 24.625,12.3
  Layer 4 w0.2: v1(24.25,19.375) 24.25,18.208 24.5,17.958 v1(24.5,17.85)
I2C1_SDA: R6.1 R9.1 U5.6 U7.3 U9.6 U10.4 | length 33.7
  Layer 1 w0.2: U5.6 v1(23.1,24.225) ; R9.1 25.69,18.7 23.225,18.7 R6.1 22.675,19.225 21.725,18.275 v1(21.725,18.25) 21.7,18.225 21.7,17.197 U7.3 20.067,17.172 19,16.104 19,13.35 20.125,12.225 22.025,12.225 U9.6 22.1,12.225 22.1,11.775 22.6,11.275 24.225,11.275 27.9,7.6 27.9,6.05 28.25,5.7 U10.4
  Layer 4 w0.2: v1(21.725,18.25) 23.1,19.625 v1(23.1,24.225)
I_MEAS: U1.14
ICSP: P3.2@11.07,3.2 U02.18 | length 9.2
  Layer 1 w0.2: U02.18 13.367,9.4 13.592,9.175 v1(13.7,9.175)
  Layer 4 w0.2: P3.2@11.07,3.2 11.07,6.545 v1(13.7,9.175)
ICSPCLK: P3.4 U02.10 | length 4.4
  Layer 1 w0.2: P3.4 8.53,5.83 9.2,6.5 U02.10
ICSPDAT: P3.5 U02.11 | length 5.8
  Layer 1 w0.2: v1(9.2,5.1) 9.2,5.6 9.6,6 U02.11
  Layer 4 w0.2: P3.5 7.26,4.36 8,5.1 v1(9.2,5.1)
LED_Gn: R13.2 U1.25 | length 2.1
  Layer 1 w0.2: U1.25 36.45,22.7 37.3,23.55 37.3,23.75 R13.2
LED_Rn: R11.2 U1.27 | length 4.1
  Layer 1 w0.2: U1.27 35.45,23.843 36.657,25.05 R11.2
MCU_DEBUG_RX: P3.2@34.125,27.25 U1.31 | length 9.2
  Layer 1 w0.2: U1.31 33.463,22.238 33.463,20.438 v1(33.475,20.425)
  Layer 4 w0.2: v1(33.475,20.425) 33.475,20.533 33.17,20.838 33.17,23.695 34.04,24.565 34.04,27.165 P3.2@34.125,27.25
MCU_DEBUG_TX: P3.3@35.395,27.25 U1.30 | length 9.7
  Layer 1 w0.2: U1.30 33.95,21.425 v1(34.95,20.425)
  Layer 4 w0.2: v1(34.95,20.425) 34.44,20.935 34.44,26.295 P3.3@35.395,27.25
NetC1_2: C1.2 U1.3 X1.1 | length 4.6
  Layer 1 w0.2: C1.2 31.1,11.6 X1.1 31.55,11.3 31.95,11.7 U1.3
NetC2_2: C2.2 U1.4 X1.2 | length 7.7
  Layer 1 w0.2: C2.2 31.04,8.44 X1.2 31.8,8.8 32.2,9.2 32.2,9.626 32.77,10.196 32.77,12.005 32.45,12.325 U1.4
NetC3_2: C3.2 U1.5 X2.1 | length 13.1
  Layer 1 w0.2: U1.5 32.95,12.391 33.3,12.041 33.3,8.584 34.775,7.109 34.775,5.2 34.1,4.525 34.1,4.3 33.6,3.8 X2.1 33.18,3.68 C3.2
NetC4_2: C4.2 U1.6 X2.3 | length 11.7
  Layer 1 w0.2: U1.6 33.45,12.456 33.725,12.181 33.725,8.725 35.75,6.7 36.8,6.7 X2.3 39.12,6.2 C4.2
NetC08_2: C08.2 U02.15 | length 1.6
  Layer 1 w0.2: U02.15 12.55,8.2 13.1,7.65 C08.2
NetC09_2: C09.2 R02.2 U02.9 | length 5.2
  Layer 1 w0.2: C09.2 7.06,6.8 7.61,6.25 8.25,6.25 8.8,6.8 U02.9
  Layer 1 w0.3: R02.2 C09.2
NetC12_2: C12.2 D3.2 D4.2 U3.2 | length 6.7
  Layer 1 w0.5: U3.2 53.125,3.625 53.55,4.05 53.55,4.1 53.75,4.3 C12.2 53.818,4.282 55.982,4.282 D4.2 D3.2
NetC13_2: C13.2 D1.1 Q1.1 R12.2 U3.1 | length 7.9
  Layer 1 w0.5: Q1.1 44.275,4.25 44.76,3.765 D1.1 ; R12.2 46.525,2.425 46.5,2.45 46.493,2.45 46.2,2.743 D1.1 ; U3.1 50.05,3.725 48.3,3.725 C13.2 48.17,3.795 46.23,3.795 D1.1
NetC22_2: C22.2 L1.2 U1.9 | length 4.7
  Layer 1 w0.3: U1.9 34.95,12.075 35.54,11.485 35.54,10.995 C22.2 37.1,10.825 L1.2
NetD02_2: D02.2 L01.2 Q01.3 | length 7.4
  Layer 1 w0.6: L01.2 11.475,21.95 13.507,19.918 Q01.3 13.732,17.675 D02.2
NetD2_2: D2.2 R11.1 | length 2.5
  Layer 1 w0.2: R11.1 39.175,25.05 39.55,25.425 40.45,25.425 D2.2
NetD2_4: D2.4 R13.1 | length 2.5
  Layer 1 w0.2: R13.1 39.65,23.925 40.35,24.625 D2.4
NetJ1_2: J1.2 R3.2 U2.1 | length 10.7
  Layer 1 w0.2: U2.1 57.25,15.35 57.5,15.6 v2(57.5,16.15)
  Layer 1 w0.4: R3.2 51.25,15.25 52,14.5 54.4,14.5 55.025,15.125 55.025,15.35 U2.1
  Layer 4 w0.2: v2(57.5,16.15) J1.2
NetJ1_3: J1.3 R4.2 U2.3 | length 8.5
  Layer 1 w0.2: U2.3 56.1,16.65 v2(56.75,16)
  Layer 1 w0.4: R4.2 53.575,18.925 55.25,17.25 U2.3
  Layer 4 w0.2: v2(56.75,16) 57.25,15.5 J1.3
NetL02_2: L02.2 U02.1 U02.3 U02.5 U02.23 U02.25 U02.26 | length 8.8
  Layer 1 w0.2: U02.5 8.4,9 8.4,9.8 ; U02.3 8.4,9.8 ; U02.1 8.4,10.6 ; U02.26 9.2,10.6 ; U02.25 9.6,10.6 ; U02.23 10.4,11 10,10.6 9.6,10.6 ; 8.4,9.8 8.4,10.6 ; 8.4,10.6 9.2,10.6 ; 9.2,10.6 9.6,10.6
NetR8_2: R8.2 U1.42 | length 3.5
  Layer 1 w0.2: R8.2 26.626,19.74 26.801,19.565 27.16,19.565 28.475,18.25 U1.42
NetR9_2: R9.2 U1.43 | length 3.2
  Layer 1 w0.2: R9.2 27.443,18.69 28.383,17.75 U1.43
NetR29_2: R29.2 U10.8 | length 3.5
  Layer 1 w0.2: R29.2 22.7,5.975 23.475,5.2 U10.8
PA15: U1.38
PH3: R7.2 U1.44 | length 3
  Layer 1 w0.2: R7.2 26.675,17.625 27.05,17.25 U1.44
PWM: Q01.1 U02.12 U02.19 | length 16.6
  Layer 1 w0.2: U02.12 10,5.549 10.4,5.149 v1(10.4,5.1) ; U02.19 12.875,9.8 v1(13.35,10.275) ; v1(12.525,14.9) 12.541,14.916 12.541,15.884 Q01.1
  Layer 4 w0.2: v1(10.4,5.1) 10.4,7.325 v1(13.35,10.275) 12.525,11.1 v1(12.525,14.9)
RESET: P4.5 R1.1 U1.7 | length 19
  Layer 1 w0.2: R1.1 P4.5 ; U1.7 33.963,13.762 33.963,15.112 v1(33.975,15.125)
  Layer 4 w0.2: P4.5 27.375,25.725 28.65,25.725 31.125,23.25 31.125,17.975 v1(33.975,15.125)
SENS_I_+: C17.2 R20.2 U10.10 | length 6.1
  Layer 1 w0.2: R20.2 20.5,6.1 C17.2 20.92,5.68 20.92,5.536 22.256,4.2 U10.10
SENS_I_-: C17.1 R22.2 U10.9 | length 4.8
  Layer 1 w0.2: R22.2 21.7,5.98 C17.1 22.82,4.7 U10.9
Solar+: C02.2 C03.2 C04.2 L01.1 L02.1 pad.2 R02.1 | length 5.2
  Layer 1 w0.3: R02.1 4.55,7.85 3.75,8.65 3.75,11.324 3.926,11.5 4.95,11.5 C03.2
  other v1: 2,23.5 2,24.5 3.25,24.5 2,25.5 3.25,25.5
SPI2_MOSI: U1.28
SPI2_SCK: U1.26
SWCLK: P4.4 U1.37 | length 7.7
  Layer 1 w0.2: P4.4 27.17,23.23 28.95,21.45 28.95,20.8 29,20.75 U1.37
SWDIO: P4.1 U1.34 | length 5.4
  Layer 1 w0.2: P4.1 31.95,26.23 U1.34
SWO: P4.6 U1.39 | length 9.9
  Layer 1 w0.2: P4.6 24.63,24.62 28.2,21.05 28.2,20.15 28.6,19.75 U1.39
USB_N: R3.1 U1.32 | length 26.1
  Layer 1 w0.2: U1.32 32.95,23.4 33.45,23.9
  Layer 1 w0.4: 33.45,23.9 34.8,23.9 37.35,26.45 44.525,26.45 46,24.975 46,22 50.25,17.75 R3.1
USB_P: R4.1 U1.33 | length 27.4
  Layer 1 w0.2: U1.33 32.45,23.95 32.75,24.25
  Layer 1 w0.4: 32.75,24.25 33.45,24.95 34.7,24.95 37,27.25 45.25,27.25 47.1,25.4 47.1,21.9 50.075,18.925 R4.1
USB_SENSE: R2.1 R30.2 U1.10 | length 22.7
  Layer 1 w0.2: U1.10 35.45,12.875 35.95,12.375 37.225,12.375 41.15,8.45 44.725,8.45 45.025,8.75 53.125,8.75 53.7,9.325 R30.2 55.025,9.325 R2.1
V_MEAS: U1.15
VCC: C05.2 C06.2 C07.2 D02.1 P3.3@9.8,3.2 R14.2 R20.1 U02.16 U02.21 U02.22 U02.24 | length 28.5
  Layer 1 w0.2: P3.3@9.8,3.2 9.8,2.2 10.3,1.7 12.284,1.7 14.5,3.916 15,4.416 15,7.6 ; U02.16 13.15,8.6 14.1,7.65 C07.2 15,7.6 ; C06.2 15,7.6 ; R14.2 20.8,8.95 20.8,8.2 20.7,8.1 20.7,8.05 20.525,7.875 R20.1 R20.1@20.475,7.875
  Layer 1 w0.6: C05.2 12.775,11.3 12.024,12.051 12.024,12.549 13.775,14.3 14.925,14.3 15.65,15.025 D02.1
VDD: C5.2 C6.2 C7.2 C8.2 C9.2 C10.2 C11.2 D1.2 D2.1 D2.3 L1.1 P4.3 Q1.2 R1.2 S1.1 S1.2 U1.1 U1.24 U1.36 U1.48 | length 36.8
  Layer 1 w0.3: R1.2 25.925,24.825 26.193,24.557 26.193,24.282 v1(26.25,24.225) ; v1(26.475,12.3) C10.2 27.26,13.647 C11.2 29.45,14.262 ; P4.3 28.44,25.51 C5.2 28.65,24.515 C6.2 29.435,23.73 29.435,23.515 30.25,22.7 30.95,22.7 U1.36 ; U1.48 29.45,14.262 ; v1(29.7,13) 30.45,13.75 U1.1 30.95,14.2 30.888,14.262 29.45,14.262 ; C9.2 37.11,9.385 L1.1 v1(38.5,9.425) ; U1.24 40.535,20.75 C8.2 41.485,20.735 41.9,21.15 C7.2 v1(43.375,21.15) ; D2.3 43.05,25.05 ; D2.1 43.05,25.05 ; v1(44.475,25.05) 43.05,25.05 ; v1(47.1,26.5) 49.925,26.5 S1.2 S1.1
  other v1: 42.95,7.475 44.425,7.475
VDD_FLASH: C14.2 C15.2 C23.2 U1.21 U1.22 U4.8 | length 20.5
  Layer 1 w0.3: U1.21 39.05,19.25 39.175,19.375 ; U1.22 38.975,19.75 39.175,19.55 39.175,19.375 ; C23.2 52.27,13.655 U4.8 49.106,13.655 48.725,14.036 C14.2 48.51,16.065 C15.2 48.51,17.95 48.085,18.375 40.5,18.375 39.5,19.375 39.175,19.375
VDD_SENSORS_FAST: C19.2 C20.2 C21.2 U1.45 U1.46 U7.1 U9.5 U10.6 | length 27.7
  Layer 1 w0.2: v1(19.7,13.9) 20.4,13.2 20.58,13.2 C20.2 20.98,12.8 U9.5 ; C19.2 23.525,15.137 23.525,15.35 ; U7.1 23.525,15.35 ; v1(24.3,8.725) 24.3,8.7 C21.2 25.4,6.25 25.35,6.2 U10.6 ; v1(24.5,15.35) 23.525,15.35 ; v1(27.375,16.525) 27.405,16.555 28.158,16.555 ; U1.46 28.297,16.25 28.158,16.389 28.158,16.555 ; U1.45 28.353,16.75 28.158,16.555
  Layer 3 - PWR w0.3: v1(19.7,13.9) 21.363,13.9 ; v1(24.3,8.725) 24.3,10.963 21.363,13.9 ; v1(27.375,16.525) 26.2,15.35 v1(24.5,15.35) 22.813,15.35 21.363,13.9
VDD_SENSORS_SLOW: C16.2 R5.2 R6.2 U1.40 U1.41 U5.1 | length 24.6
  Layer 1 w0.2: U5.1 20.204,23.425 C16.2 ; R6.2 v1(19.625,20.175) 19.125,20.675 19.125,23.292 19.242,23.409 19.78,23.409 C16.2 ; 28.283,19.09 28.443,19.25 U1.40 ; U1.41 28.541,18.75 27.412,19.879 27.412,20.637 26.749,21.3 R5.2 24.25,24.275 23.65,24.875 21.246,24.875 C16.2
pads on no net: J1.4 U1.29 U2.4 U02.13 U02.14 U02.17 U02.20 U5.5 U9.3 U10.3

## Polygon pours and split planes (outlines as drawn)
5V_USB on Layer 1 "NONET_L-01_P-001" (solid, pour order 21): 62,11.25 63.25,11.25 63.25,9.25 62,9.25
Solar+ on Layer 1 "SOLAR+_L01_P016" (solid, pour order 16): 1.25,22.75 1.25,26.25 4.5,26.25 4.5,24.475 5.475,23.5 5.475,22.75
GND on Layer 1 "GND_L01_P014" (solid, pour order 14): 13.1,12.55 15,12.55 15,13 15.65,13 15.65,13.9 17,13.9 17,12 13.1,12
GND on Layer 1 "GND_L01_P013" (solid, pour order 13): 2.9,22.25 2.9,5 -0.75,5 -0.75,22.25
VDD on Layer 1 "VDD_L01_P008" (solid, pour order 8): 46.75,7.4 46.75,8.05 42.15,8.05 42.15,6.15 46.749,6.15 46.749,7.255
GND on Layer 1 "GND_L01_P007" (solid, pour order 7): 54.16,5.056 47.75,5.056 47.75,8.025 54.25,8.025 54.25,5.325
VCC on Layer 1 "VCC_L01_P004" (solid, pour order 4): 9.9,11.3 10.775,11.3 11.575,10.5 12.65,10.5 13.15,11 13.825,11 14.3,10.525 16.125,10.525 17.925,8.725 20.775,8.725 20.775,10.05 20.725,10.1 18.725,10.1 17.225,11.6 13.025,11.6 11.95,12.675 10.375,12.675 9.9,12.2
GND on Layer 1 "GND_L01_P003" (solid, pour order 3): 8.887,11.822 6.791,11.822 6.468,11.498 6.468,10.932 6.037,10.501 4.51,10.501 4.51,9.143 5.322,8.332 5.322,7.595 6.69,7.595 7.575,8.479 7.575,10.921 7.914,11.26 8.888,11.26
NetL02_2 on Layer 1 "NETL02_2_L01_P002" (solid, pour order 2): 10,15.9 9.925,15.9 9.925,13.5 9.051,12.626 9.051,11.153 9.702,11.153 9.702,12.252 10.9,13.45 10.9,15.883
Solar+ on Layer 1 "SOLAR+_L01_P000" (solid, pour order 0): 3.5,23.5 3.5,11 5.998,11 5.998,23.5
GND on Layer 4 "GND_L04_P020" (solid, pour order 20): 7.75,16.25 6,16.25 3.25,19 0,19 0,7.5 1,7.5 6.75,13.25 8.25,13.25
Solar+ on Layer 4 "SOLAR+_L04_P015" (solid, pour order 15): 8.75,22.5 5,26.25 3.5,26.25 3.5,21.25 8.75,21.25
GND on Layer 4 "GND_L04_P011" (solid, pour order 11): 63.5,6.3 63.5,0 57.7,0 57.7,6.3
EXT_BAT on Layer 4 "EXT_BAT_L04_P006" (solid, pour order 6): 58.55,8.675 58.55,7.25 63.15,7.25 63.15,8.75 58.65,8.75
5V_USB on Layer 4 "5V_USB_L04_P005" (solid, pour order 5): 58.258,17 58.908,17.65 60.425,17.65 63.325,14.75 63.325,9.175 61.95,9.175 61.95,15 60.325,16.625 58.25,16.625
GND on Layer 2 - GND "GND_L02_P009" (solid, pour order 9): 15.425,13.5 18.625,13.5 18.625,29.85 65.475,29.85 65.475,-1.95 18.7,-1.95 18.7,9.875 15.6,9.875 15.6,-2.175 10.5,-2.175 10.5,13.5
GND on Layer 2 - GND "GND_L02_P019" (solid, pour order 19): 5.25,13 5.25,29.5 -1.5,29.5 -1.5,-1.25 12.75,-1.25 12.75,13
GND on Layer 2 - GND "GND_L02_P018" (solid, pour order 18): 10.5,11 10.5,18.75 12.07,18.75 12.07,25.75 5.25,25.75 5.25,31 15.5,31 15.5,11
VDD on Layer 3 - PWR "VDD_L03_P012" (solid, pour order 12): 25.9,6.9 25.9,29.6 47.625,29.6 47.625,6.9

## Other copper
Layer 4:
  rectangle net Solar+: 1.25,22.75 5,26.25

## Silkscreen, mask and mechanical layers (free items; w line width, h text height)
Mechanical 1:
  circle w0.013: c6.91,21.922 r2.5
  circle w0.013: c6.942,14.422 r2.5
  circle w0.013: c6.91,6.922 r2.5
  circle w0.013: c6.91,6.922 r2.5
  circle w0.013: c6.942,14.422 r2.5
  circle w0.013: c6.91,21.922 r2.5
  lines w0.013: 58.883,-0.194 ccw(c58.907,4.696) 63.797,4.678 63.799,5.557 63.803,6.681 63.836,14.422 63.803,22.163 63.799,23.046 63.797,24.165 ccw(c58.907,24.148) 58.883,29.037 ; 58.883,-0.194 57.764,-0.187 56.881,-0.183 6.881,0.029 5.757,0.033 4.878,0.035 cw(c4.896,4.925) 0.006,4.949 0.013,6.068 0.017,6.951 0.049,14.422 0.017,21.893 0.012,23.016 0.006,23.895 cw(c4.896,23.919) 4.878,28.809 5.998,28.811 6.881,28.815 56.881,29.027 58.004,29.032 58.883,29.037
